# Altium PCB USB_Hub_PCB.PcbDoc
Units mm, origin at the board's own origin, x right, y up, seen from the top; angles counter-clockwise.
Board outline 110 x 90 mm, 2 copper layers (Top Layer, Bottom Layer); 74 components, 53 nets, 295 pads, 340 vias.
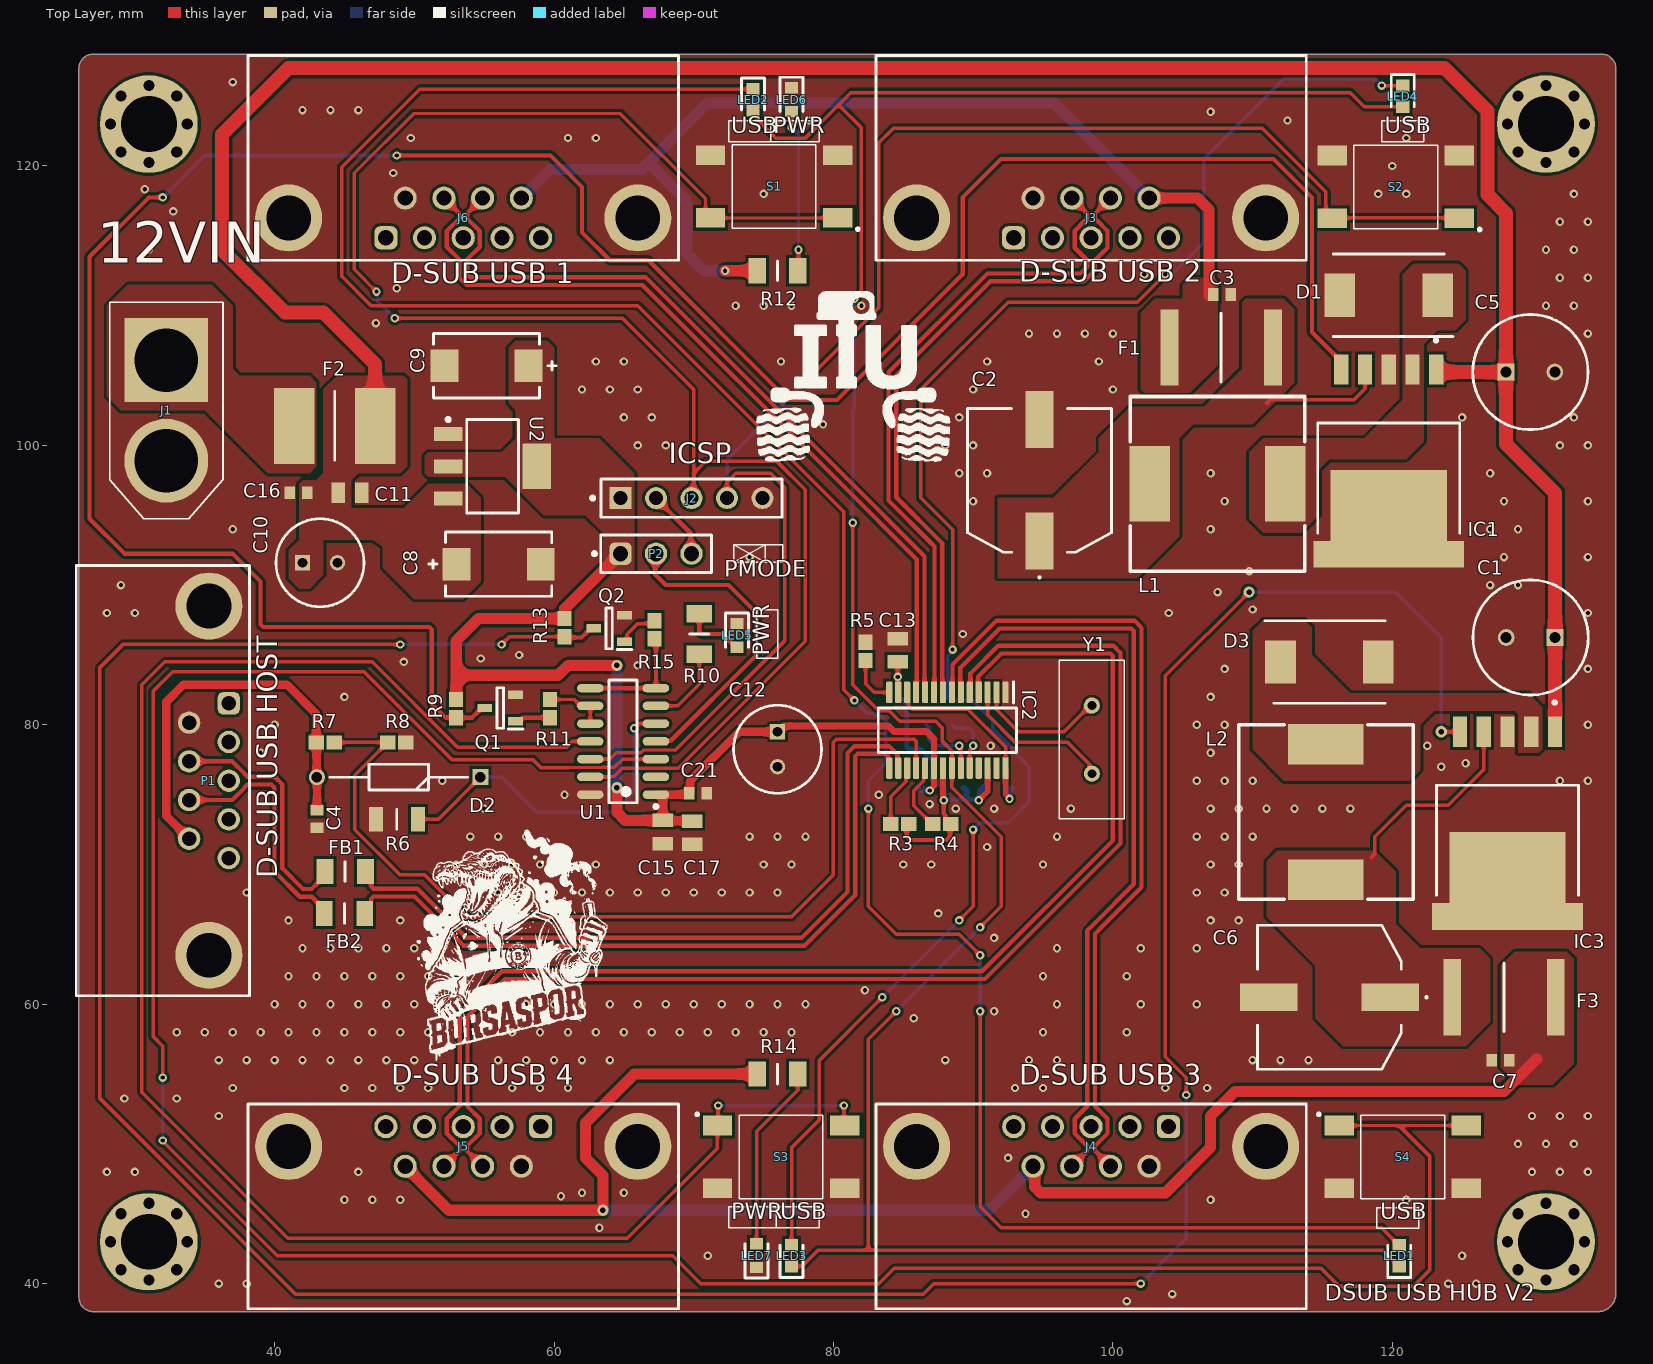
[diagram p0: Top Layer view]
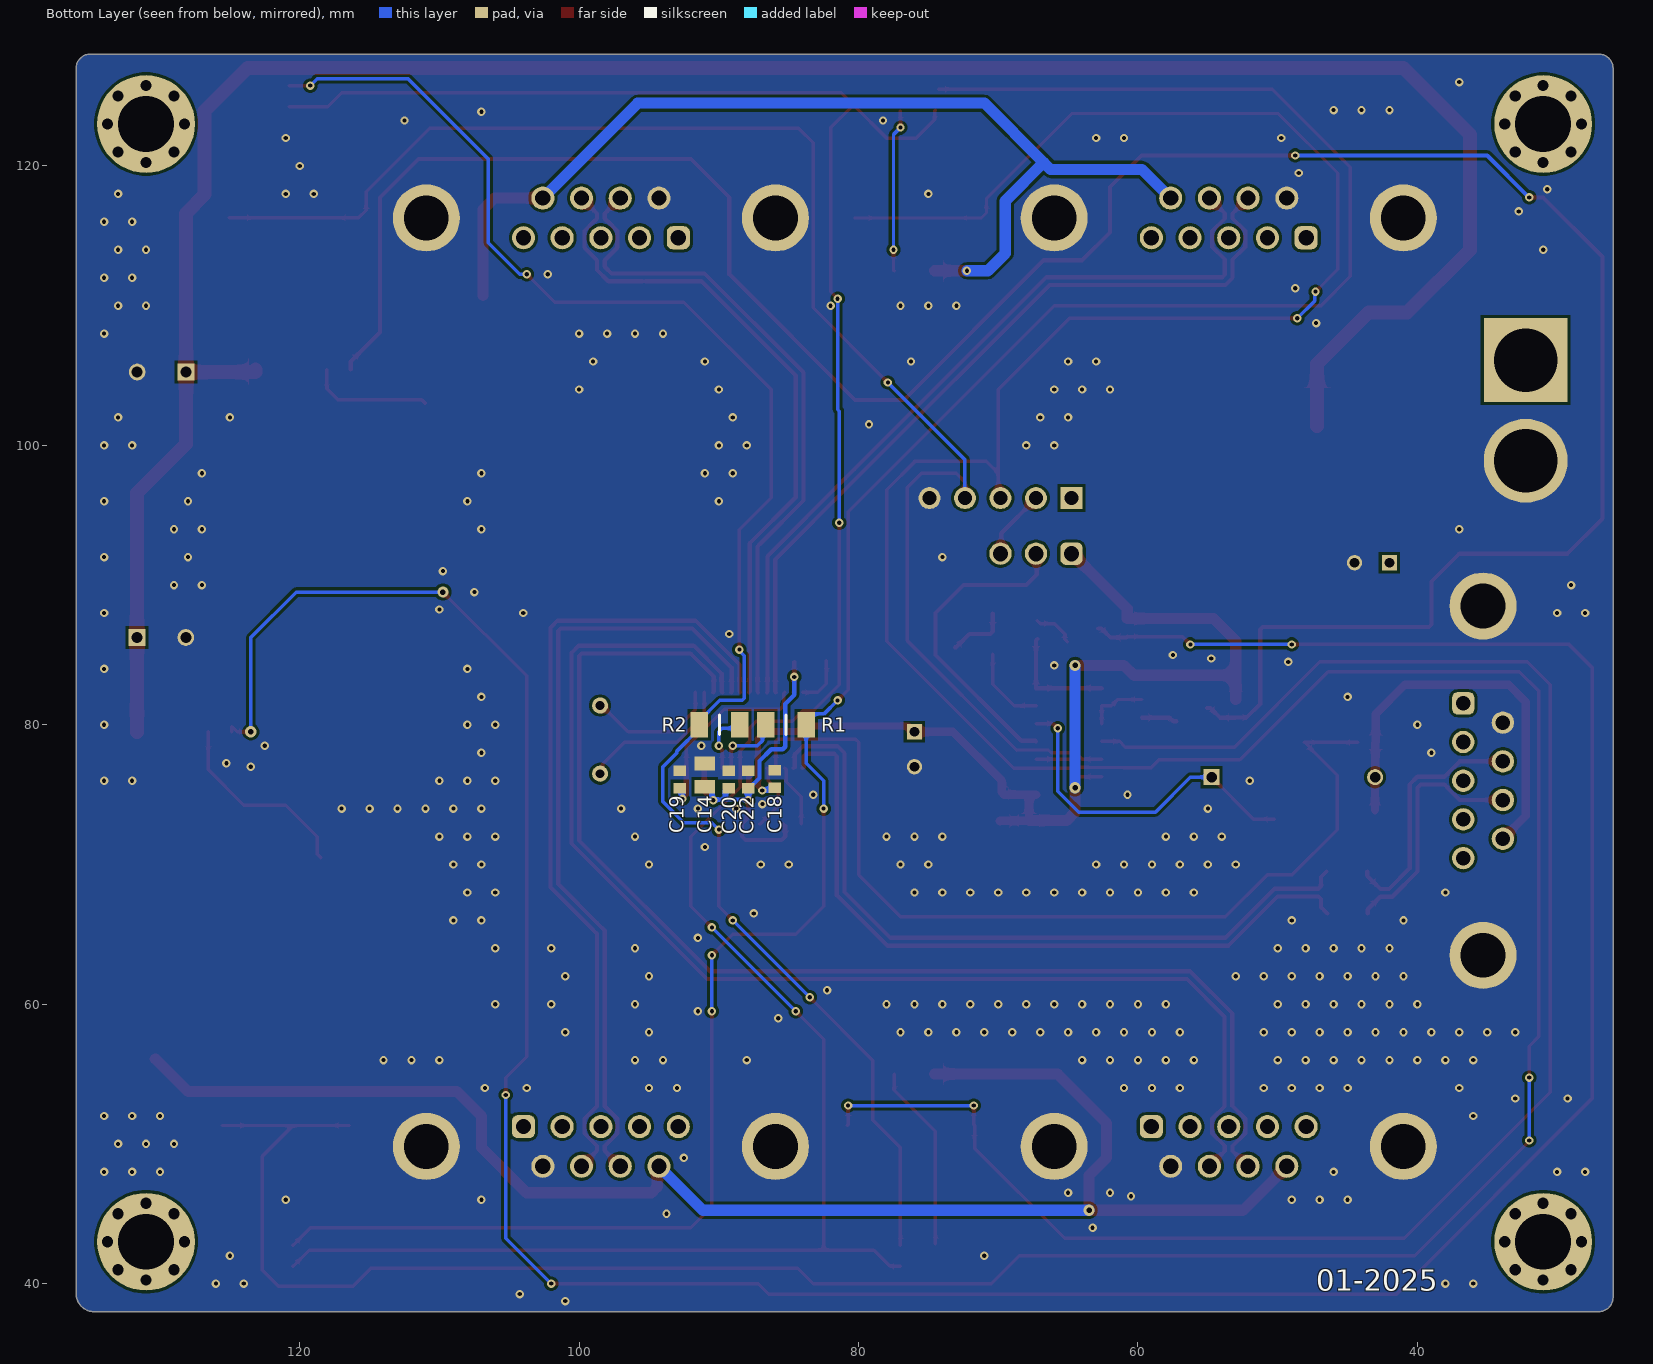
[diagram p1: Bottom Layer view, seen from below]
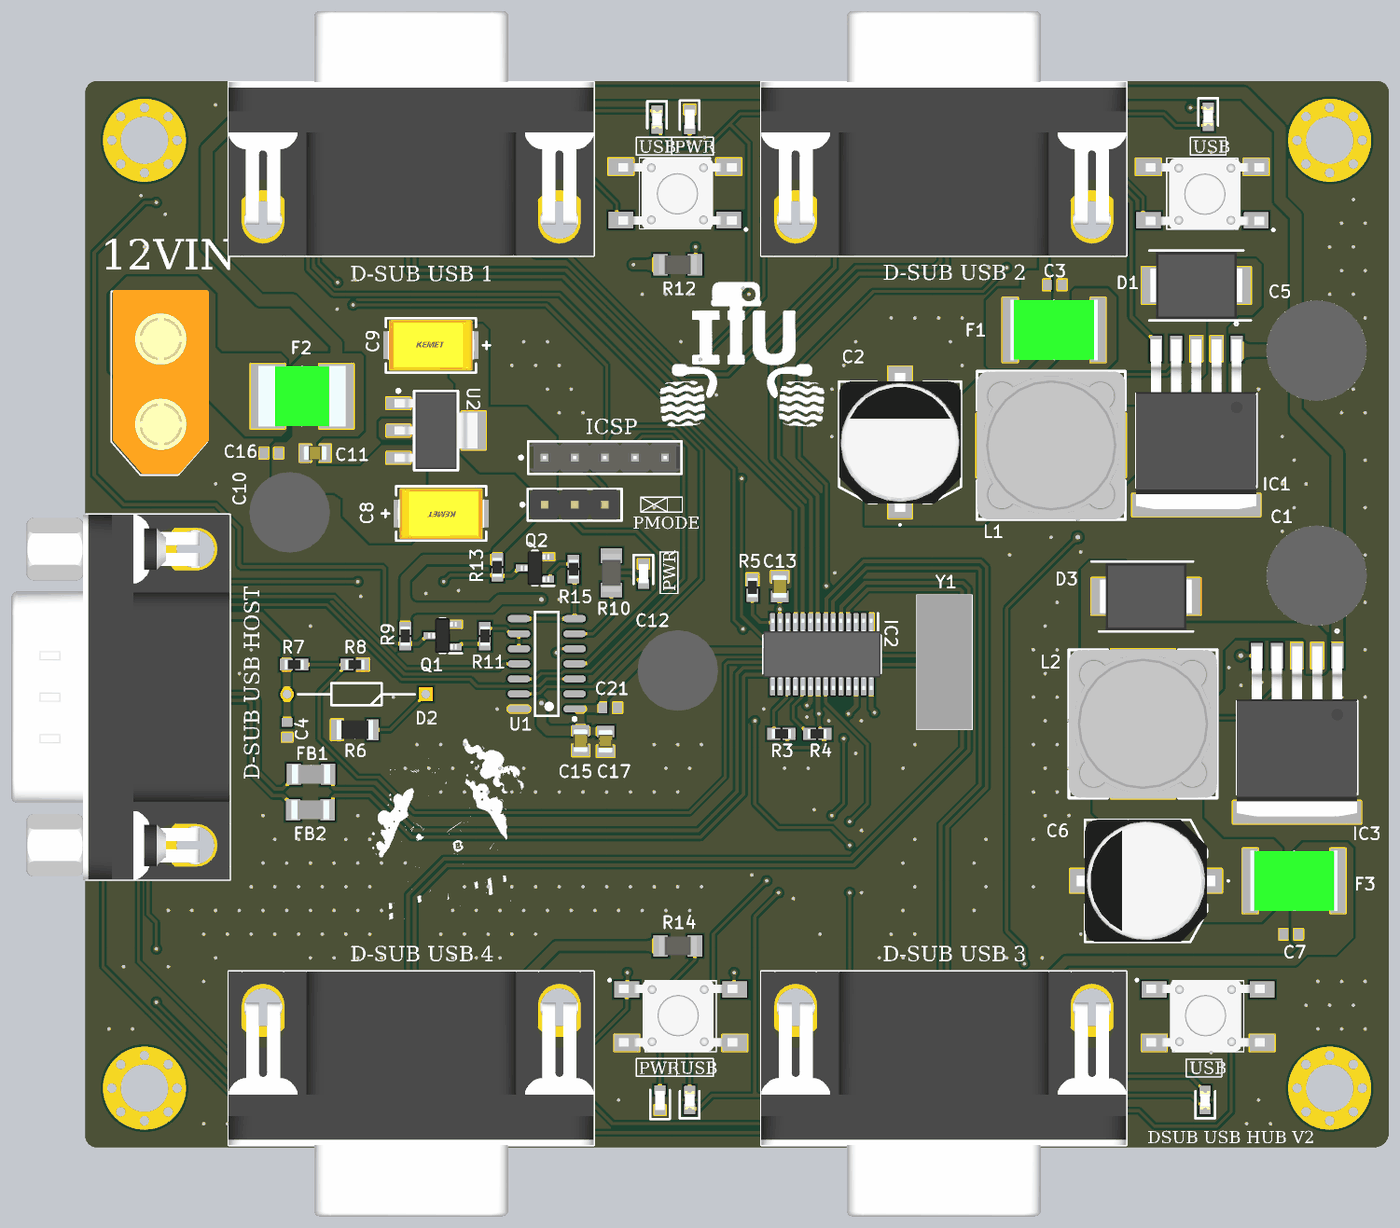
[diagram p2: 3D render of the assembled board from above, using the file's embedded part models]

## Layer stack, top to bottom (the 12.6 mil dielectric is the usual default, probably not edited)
Top Solder: solder mask 0.2, Solder Resist, Dk 3.5
Top Layer: signal copper 0.0356
Dielectric 1: dielectric 0.32, FR-4, Dk 4.8
Bottom Layer: signal copper 0.0356
Bottom Solder: solder mask 0.2, Solder Resist, Dk 3.5

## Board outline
27,38 cw(c27,39) 26,39 26,127 cw(c27,127) 27,128 135,128 cw(c135,127) 136,127 136,39.27 cw(c134.73,39.27) 134.73,38

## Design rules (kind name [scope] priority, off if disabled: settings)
Clearance [All] p1: gap=0.2 ignorepadtopadclearanceinfootprint=FALSE
DiffPairsRouting [All] p1: maxlimit=0.25 minlimit=0.25 mostfreqgap=0.25 toplayer_minwidth=0.305 toplayer_maxwidth=0.305 toplayer_prefwidth=0.305 bottomlayer_minwidth=0.305 bottomlayer_maxwidth=0.305 bottomlayer_prefwidth=0.305 impedanceprofiledriven=TRUE impedanceprofileid={82985F45-E5DD-44E9-867F-111D7A09A1A5} impedanceprofilevalue=90.000000 maxuncoupledlength=12.7
HoleSize [All] p1: absolutevalues=TRUE maxlimit=5 minlimit=0.3 maxpercent=80.000 minpercent=20.000
HoleToHoleClearance [All] p1: gap=0.25 allowstackedmicrovias=TRUE
MinimumSolderMaskSliver [All] p1: minsoldermaskwidth=0.25
PolygonConnect [All] p1: connectstyle=Direct reliefconductorwidth=0.254 reliefentries=4 polygonreliefangle="90 Angle" airgapwidth=0.254
RoutingVias [All] p1: holewidth=0.3 width=0.6 viastyle="Through Hole" minholewidth=0.3 minwidth=0.5 maxholewidth=0.8 maxwidth=1
SilkToSilkClearance [All] p1: silktosilkclearance=0.13
SilkToSolderMaskClearance [IsPad] p1: minsilkscreentomaskgap=0.13 clearancetoexposedcopper=TRUE
SolderMaskExpansion [All] p1: expansion=0.102 istentingtop=FALSE
SupplyNets "Schematic Supply Nets_4" [InNet('+12V')] p1: voltage=0.000
SupplyNets "Schematic Supply Nets_3" [InNet('GND')] p2: voltage=0.000
SupplyNets "Schematic Supply Nets_2" [InNet('+3V3')] p3: voltage=0.000
SupplyNets "Schematic Supply Nets_1" [InNet('+1V8')] p4: voltage=0.000
SupplyNets "Schematic Supply Nets" [InNet('+5V')] p5: voltage=0.000
Width [All] p1: maxlimit=1 minlimit=0.2 preferedwidth=0.25 minimp=50.000000 maximp=50.000000 favimp=50.000000
24 further rules are at their usual default settings.

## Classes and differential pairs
differential pair HOSTCONN_D: +HOSTCONN_D_P -HOSTCONN_D_N
differential pair USB4_D: +USB4_D_P -USB4_D_N
differential pair USB3_D: +USB3_D_P -USB3_D_N
differential pair USB2_D: +USB2_D_P -USB2_D_N
differential pair USB1_D: +USB1_D_P -USB1_D_N
differential pair HOST_D: +HOST_D_P -HOST_D_N

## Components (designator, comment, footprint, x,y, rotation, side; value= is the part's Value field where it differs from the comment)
C1 "UPW1E471MPD6" CAPPRD350W60D825H2200 131.65,86.25 r180 top
C2 "220µF 50V" EEEFK1V331P 94.75,97.5 r0 top
C3 "VJ0603Y104JXJAC" CAPC1608X92X38LL15T08 107.8,110.8 r180 top
C4 "VJ0603Y104JXJAC" CAPC1608X92X38LL15T08 43.034,73.25 r90 top
C5 "UPW1E471MPD6" CAPPRD350W60D825H2200 128.138,105.25 r0 top
C6 "220µF 50V" EEEFK1V331P 115.5,60.5 r90 top
C7 "VJ0603Y104JXJAC" CAPC1608X92X38LL15T08 127.75,56 r0 top
C8 "10uF Tantal" FP-T491D-MFG 56.035,91.5 r180 top
C9 "10uF Tantal" FP-T491D-MFG 55.165,105.7 r0 top
C10 "860020473008" CAPPRD250W52D630H1250 42,91.6 r0 top
C11 "CL21A106KAYNNNG" CAPC2012X145N 45.4,96.6 r180 top
C12 "860020473008" CAPPRD250W52D630H1250 76,79.5 r270 top
C13 "CL21A106KAYNNNG" CAPC2012X145N 84.6,85.33 r270 top
C14 "CL21A106KAYNNNG" CAPC2012X145N 91,76.4 r270 bottom
C15 "CL21A106KAYNNNG" CAPC2012X145N 67.8,72.33 r90 top
C16 "VJ0603Y104JXJAC" CAPC1608X92X38LL15T08 41.7,96.6 r0 top
C17 "CL21A106KAYNNNG" CAPC2012X145N 69.9,72.27 r90 top
C18 "VJ0603Y104JXJAC" CAPC1608X92X38LL15T08 86,76.125 r270 bottom
C19 "VJ0603Y104JXJAC" CAPC1608X92X38LL15T08 92.8,76.1 r270 bottom
C20 "VJ0603Y104JXJAC" CAPC1608X92X38LL15T08 89.3,76.1 r270 bottom
C21 "VJ0603Y104JXJAC" CAPC1608X92X38LL15T08 70.3,75.1 r180 top
C22 "VJ0603Y104JXJAC" CAPC1608X92X38LL15T08 87.9,76.1 r270 bottom
D1 "B540C-13-F" DIOM7959X250N 119.75,110.75 r180 top
D2 "1N4148,133" DIOAD1165W56L425D185 54.734,76.25 r180 top
D3 "B540C-13-F" DIOM7959X250N 115.5,84.5 r0 top
F1 "MF-LSMF300X-2" FUSC7451X85N 107.75,107 r180 top
F2 "2920L600_16MR" FUSC7451X160N 44.3,101.4 r0 top
F3 "MF-LSMF300X-2" FUSC7451X85N 128,60.5 r0 top
FB1 "HI1206T500R-10" BEADC3216X130N 45.05,69.5 r0 top
FB2 "HI1206T500R-10" BEADC3216X130N 45,66.5 r180 top
IC1 "LM2596S-5.0" KTT0005B 119.75,92.964 r90 top
IC2 "FE1.1S" SOP64P600X175-28N 88.16,79.612 r270 top
IC3 "LM2596S-5.0" KTT0005B 128.25,67.039 r90 top
J1 "XT60-M" XT60-M-Footprint-1 32.25,102.5 r270 top
J2 "22-28-4050" FP-22-28-4050-MFG 69.843,96.225 r0 top
J3 "618009233821" 618009233821 98.445,120.625 r180 top
J4 "618009233821" 618009233821 98.445,45.475 r0 top
J5 "618009233821" 618009233821 53.505,45.475 r0 top
J6 "618009233821" 618009233821 53.505,120.625 r180 top
L1 "SRR1260-330M" SRR1260-150M 107.5,97.25 r180 top
L2 "SRR1260-330M" SRR1260-150M 115.25,73.75 r270 top
LED1 "LTST-C190GKT" LEDC1608X90N 120.499,42 r90 top
LED2 "LTST-C190GKT" LEDC1608X90N 74.25,124.75 r270 top
LED3 "LTST-C190GKT" LEDC1608X90N 77,42 r90 top
LED4 "LTST-C190GKT" LEDC1608X90N 120.75,125 r270 top
LED5 "TLMS1000-GS08" LEDC1608X65N 73.1,86.4 r270 top
LED6 "TLMS1000-GS08" LEDC1608X65N 77,124.75 r270 top
LED7 "TLMS1000-GS08" LEDC1608X65N 74.5,42 r90 top
P1 "618009231221" 618009231221 32,76 r270 top
P2 "61300311121" 61300311121 67.303,92.25 r0 top
Q1 "PMBT3904,235" SOT95P230X110-3N 56.15,81.2 r180 top
Q2 "PMBT3904,235" SOT95P230X110-3N 63.95,86.9 r180 top
R1 "RMCF1206JT2K20" RESC3216X70N 85.2,80 r0 bottom
R2 "RMCF1206JT2K20" RESC3216X70N 89.95,80 r180 bottom
R3 "RC0603FR-07100KL" RESC1608X55N 84.75,72.9 r0 top
R4 "RC0603FR-07100KL" RESC1608X55N 87.75,72.9 r0 top
R5 "RC0603JR-072K7L" RESC1608X55N 82.3,85.25 r270 top
R6 "RC1206FR-0747KL" RESC3116X65N 48.75,73.25 r0 top
R7 "RC0603FR-0751KL" RESC1608X55N 43.634,78.75 r0 top
R8 "RC0603FR-07100KL" RESC1608X55N 48.75,78.75 r180 top
R9 "RC0603FR-0724K9L" RESC1608X55N 53,81.161 r90 top
R10 "RMCF1206JT2K20" RESC3216X70N 70.4,86.5 r90 top
R11 "10K" RESC1608X55N 59.722,81.161 r270 top
R12 "CR1206-JW-512ELF" RESC3216X70N 75.999,112.5 r0 top
R13 "RC0603FR-0724K9L" RESC1608X55N 60.765,86.961 r90 top
R14 "CR1206-JW-512ELF" RESC3216X70N 76.001,55 r0 top
R15 "10K" RESC1608X55N 67.2,86.8 r90 top
S1 "TL3301AF160QG" TL3301AF160QG 75.75,118.53 r90 top
S2 "TL3301AF160QG" TL3301AF160QG 120.25,118.5 r90 top
S3 "TL3301AF160QG" TL3301AF160QG 76.25,49.07 r270 top
S4 "TL3301AF160QG" TL3301AF160QG 120.748,49.07 r270 top
U1 "PIC16F630-I/SL" SOIC-SL14_L 64.944,78.814 r180 top
U2 "LM1117IMP-5.0-NOPB" DCY0004A_M 55.6,98.5 r0 top
Y1 "ECS-120-18-4X-CKM" ECS120184XCKM 98.5,76.5 r90 top

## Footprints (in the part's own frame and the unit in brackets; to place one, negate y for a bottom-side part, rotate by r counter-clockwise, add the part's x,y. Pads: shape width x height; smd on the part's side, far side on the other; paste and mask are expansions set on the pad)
61300311121 [mm] "Pin Header, pitch 2.54 mm, THT, Vertical, single row, 3p"
  rrect50% 1.6x1.6 hole 1.1: 1(-2.54,0)
  round 1.6 hole 1.1: 2(0,0) 3(2.54,0)
  silkscreen extent -4.53,-1.35 3.96,1.35, body extent -3.81,-1.27 3.81,1.27, height 8.57
618009231221 [mm] "9 pins, right angled, 8.08mm, with hex screw"
  rrect50% 1.6x1.6 hole 1.04: 1(-5.54,4.72)
  round 1.6 hole 1.04: 2(-2.77,4.72) 3(0,4.72) 4(2.77,4.72) 5(5.54,4.72) 6(-4.155,1.88) 7(-1.385,1.88) 8(1.385,1.88) 9(4.155,1.88)
  round 4.8 hole 3.2: M1(-12.5,3.3) M2(12.5,3.3)
  silkscreen extent -15.4,-6.2 15.4,6.2, body extent -15.4,-12.2 15.4,6.2, height 12.57
618009233821 [mm] "09p 10.3mm bracket, board lock & UNC4-40 Rivet without hex screw"
  rrect50% 1.65x1.65 hole 1.09: 1(5.54,5.765)
  round 1.65 hole 1.09: 2(2.77,5.765) 3(0,5.765) 4(-2.77,5.765) 5(-5.54,5.765) 6(4.155,2.925) 7(1.385,2.925) 8(-1.385,2.925) 9(-4.155,2.925)
  round 4.8 hole 3.2: M1(-12.495,4.345) M2(12.495,4.345)
  silkscreen extent -15.4,-7.27 15.4,7.37, body extent -15.41,-13.27 15.41,7.37, height 12.57
BEADC3216X130N [mm]
  rect 1.2x1.8 smd: 1(-1.45,0) 2(1.45,0)
  silkscreen extent 0,-0.7 0,0.7, body extent -1.6,-0.8 1.6,0.8, height 1.3
CAPC1608X92X38LL15T08 [mm] "Chip Capacitor, 2-Leads, Body 1.60x0.80mm, IPC High Density"
  rect 0.75x0.9 smd: 1(-0.625,0) 2(0.625,0)
  body extent -0.87,-0.48 0.87,0.48, height 0.92
CAPC2012X145N [mm]
  rect 0.97x1.47 smd: 1(-0.83,0) 2(0.83,0)
  body extent -1,-0.63 1,0.63, height 1.45
CAPPRD250W52D630H1250 [mm]
  rect 1.1x1.1 hole 0.7: 1(0,0)
  round 1.1 hole 0.7: 2(2.5,0)
  silkscreen extent -1.9,-3.15 4.4,3.15, body extent -2.14,-3.4 4.65,3.4, height 12.5
CAPPRD350W60D825H2200 [mm]
  rect 1.2x1.2 hole 0.8: 1(0,0)
  round 1.2 hole 0.8: 2(3.5,0)
  silkscreen extent -2.38,-4.12 5.87,4.12, body extent -2.49,-4.25 6,4.25, height 22
DCY0004A_M [mm] "SOT223, 4-Leads, Body 6.7x3.7mm, Pitch 2.3mm, IPC Low Density"
  rrect10% 2.05x1 smd: 1(-3.175,2.3) 2(-3.175,0) 3(-3.175,-2.3)
  rrect5% 2.05x3.25 smd: 4(3.175,0)
  silkscreen extent -3.3,-3.35 1.85,3.47, body extent -3.5,-3.25 3.5,3.25, height 1.62
DIOAD1165W56L425D185 [mm]
  rect 1.15x1.15 hole 0.75: 1(0,0)
  round 1.15 hole 0.75: 2(11.7,0)
  silkscreen extent 0.92,-0.92 10.78,0.92
DIOM7959X250N [mm]
  rect 2.2x3.1 smd: 1(-3.5,0) 2(3.5,0)
  silkscreen extent -4.6,-2.95 3.97,2.95, body extent -3.9,-2.81 3.9,2.81, height 2.5
ECS120184XCKM [mm]
  round 1.155 hole 0.63: 1(0,0) 2(4.88,0)
  silkscreen extent -3.23,-2.32 8.12,2.32, body extent -3.23,-2.32 8.12,2.32, height 3.5
EEEFK1V331P [mm]
  rect 2x4.1 smd: 1(0,-4.35) 2(0,4.35)
  silkscreen extent -5.15,-7 5.15,5.15, body extent -5.15,-5.85 5.15,5.85, height 10.2
FP-22-28-4050-MFG [mm]
  rect 1.57x1.57 hole 1.02 paste-2539.97 mask+0: 1(-5.08,0)
  round 1.57 hole 1.02 paste-2539.97 mask+0: 2(-2.54,0) 3(0,0) 4(2.54,0) 5(5.08,0)
  silkscreen extent -7.2,-1.37 6.48,1.37, body extent -6.58,-1.47 6.58,1.47, height 0.25
FP-T491D-MFG [mm]
  rect 1.99x2.33 smd paste+0 mask+0: 1(-3.01,0) 2(3.01,0)
  silkscreen extent -3.8,-2.3 5,2.3, body extent -4.13,-2.42 4.13,2.42, height 0.25
FUSC7451X85N [mm]
  rect 1.28x5.45 smd: 1(-3.705,0) 2(3.705,0)
  silkscreen extent 0,-2.46 0,2.46, body extent -3.68,-2.56 3.68,2.56, height 0.85
FUSC7451X160N [mm]
  rect 2.9x5.45 smd: 1(-2.89,0) 2(2.89,0)
  silkscreen extent 0,-2.46 0,2.46, body extent -3.68,-2.56 3.68,2.56, height 1.6
KTT0005B [mm]
  rect 2.16x1.02 smd: 1(12.461,-3.4) 2(12.461,-1.7) 3(12.461,0) 4(12.461,1.7) 5(12.461,3.4)
  rect 1.91x1.235 smd: 6(-0.754,4.782) 6(-0.754,-4.782)
  rect 6.99x8.33 smd: 6(1.786,0)
  silkscreen extent 0.76,-5.08 14.68,5.08, body extent -1.11,-5.08 13.24,5.08, height 4.72
LEDC1608X65N [mm]
  rect 0.8x0.95 smd: 1(-0.85,0) 2(0.85,0)
  silkscreen extent -1.6,-0.82 0.85,0.82, body extent -0.83,-0.4 0.77,0.4, height 0.65
LEDC1608X90N [mm]
  rect 0.9x0.95 smd: 1(-0.75,0) 2(0.75,0)
  silkscreen extent -1.55,-0.82 0.75,0.82, body extent -0.82,-0.4 0.78,0.4, height 0.8
RESC1608X55N [mm]
  rect 1.1x1 smd: 1(-0.65,0) 2(0.65,0)
  body extent -0.8,-0.4 0.8,0.4, height 0.55
RESC3116X65N [mm]
  rect 1x1.75 smd: 1(-1.5,0) 2(1.5,0)
  silkscreen extent 0,-0.7 0,0.7, body extent -1.55,-0.8 1.55,0.8, height 0.65
RESC3216X70N [mm]
  rect 1.25x1.8 smd: 1(-1.45,0) 2(1.45,0)
  silkscreen extent 0,-0.7 0,0.7, body extent -1.6,-0.8 1.6,0.8, height 0.55
SOIC-SL14_L [mm] "SOIC, 14-Leads, Body 8.7x3.9mm, Pitch 1.27mm, IPC High Density"
  oval 1.9x0.6 smd: 1(-2.35,3.81) 2(-2.35,2.54) 3(-2.35,1.27) 4(-2.35,0) 5(-2.35,-1.27) 6(-2.35,-2.54) 7(-2.35,-3.81) 8(2.35,-3.81) 9(2.35,-2.54) 10(2.35,-1.27) 11(2.35,0) 12(2.35,1.27) 13(2.35,2.54) 14(2.35,3.81)
  silkscreen extent -2.48,-4.4 1,4.78, body extent -2,-4.38 2,4.38, height 1.75
SOP64P600X175-28N [mm]
  rrect30% 1.525x0.44 smd mask+0.1: 1(-2.712,4.16) 2(-2.712,3.52) 3(-2.712,2.88) 4(-2.712,2.24) 5(-2.712,1.6) 6(-2.712,0.96) 7(-2.712,0.32) 8(-2.712,-0.32) 9(-2.712,-0.96) 10(-2.712,-1.6) 11(-2.712,-2.24) 12(-2.712,-2.88) 13(-2.712,-3.52) 14(-2.712,-4.16) 15(2.712,-4.16) 16(2.712,-3.52) 17(2.712,-2.88) 18(2.712,-2.24) 19(2.712,-1.6) 20(2.712,-0.96) 21(2.712,-0.32) 22(2.712,0.32) 23(2.712,0.96) 24(2.712,1.6) 25(2.712,2.24) 26(2.712,2.88) 27(2.712,3.52) 28(2.712,4.16)
  silkscreen extent -3.47,-4.95 1.6,4.95, body extent -3,-4.95 3,4.95, height 1.75
SOT95P230X110-3N [mm]
  rect 1.05x0.6 smd: 1(-1.1,0.95) 2(-1.1,-0.95) 3(1.1,0)
  silkscreen extent -1.63,-1.45 0.23,1.5, body extent -1.2,-1.45 1.2,1.45, height 0.95
SRR1260-150M [mm]
  rect 2.9x5.4 smd: 1(-4.85,0) 2(4.85,0)
  silkscreen extent -6.25,-6.25 6.25,6.25, body extent -6.25,-6.25 6.25,6.25, height 6
TL3301AF160QG [mm]
  rect 1.4x2.1 smd: 1(-2.25,-4.55) 2(-2.25,4.55) 3(2.25,-4.55) 4(2.25,4.55)
  silkscreen extent -3.1,-6.05 3,3, body extent -3.05,-5.22 2.95,4.78, height 5.1
XT60-M-Footprint-1 [mm]
  round 6 hole 4.55: N(3.6,0)
  rect 6x6 / inner round 6 / far side rect 6x6 hole 4.55: P(-3.6,0)
  silkscreen extent -7.75,-4.05 7.75,4.05, body extent -7.88,-3.92 7.62,4.18, height 16

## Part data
C1 C5: "Capacitor Polarised", Manufacturer_Name=Nichicon, Mouser Part Number=647-UPW1E471MPD6
C2 C6: library part EEE-1HA221P, "Capacitor Polarised / EEE-1HA221P", Manufacturer_Name=Panasonic, Mouser Part Number=667-EEE-1HA221P
C3 C4 C7 C16 C18 C19 C20 C21 C22: library part CMP-001-00083-1, "Cap Ceramic 0.1uF 16V X7R 5% SMD 0603 150°C Paper T/R"
C8 C9: library part CMP-001-00086-1, "Cap Tant Solid 10uF 25V D CASE 10% (7.3 X 4.3 X 2.8mm) Inward L SMD 7343-31 1 Ohm 125C T/R / T491D106K025AT"
C10 C12: "Capacitor Polarised", Manufacturer_Name="Wurth Elektronik", Mouser Part Number=710-860020473008
C11 C13 C14 C15 C17: "Capacitor", Manufacturer_Name=SAMSUNG, Mouser Part Number=187-CL21A106KAYNNNG
D1 D3: "Diode", Manufacturer_Name="Diodes Incorporated", Mouser Part Number=621-B540C-F
D2: "Diode", Manufacturer_Name=Nexperia, Mouser Part Number=771-1N4148,133
F1 F3: "Fuse", Manufacturer_Name=Bourns, Mouser Part Number=652-MF-LSMF300X-2
F2: "Resettable Fuse", Arrow Part Number=2920L600/16MR, Manufacturer_Name=LITTELFUSE, Mouser Part Number=576-2920L600/16MR
FB1 FB2: "Ferrite Bead", Manufacturer_Name="Laird Technologies", Mouser Part Number=N/A
IC1 IC3: "Integrated Circuit", Manufacturer_Name="Texas Instruments", Mouser Part Number=926-LM2596S-50
IC2: "Integrated Circuit", Manufacturer_Name="JFD IC"
J1: library part CMP-002-00074-2, "XT60 Male Connector"
J2: library part CMP-00257-00278173-1, "22-28-4050 KK® 254 Breakaway Header, Vertical, 5 Circuits, Tin (Sn) Plating, Mating Pin Length 6.09mm", Color=Black, Contact Resistance=20mΩ, Current Rating=4A, Flammability Rating="UL94 V-0", Max Operating Temperature=75°C, Max Voltage Rating (DC)=250.25kV, Min Operating Temperature=0°C, Voltage Rating=250V
J3 J4 J5 J6: library part CMP-03913-89205522-1, "618009233821 D-Sub, 10.30mm Female Angled PCB Connector without Hex Screw, 9 pins", Contact Resistance=30mΩ, Current Rating=3A, Max Operating Temperature=105°C, Min Operating Temperature=-55°C, Operating Supply Voltage=125V, Insulation Resistance=5GΩ
L1 L2: "Inductor", Manufacturer_Name=Bourns, Mouser Part Number=652-SRR1260-330M
LED1 LED2 LED3 LED4: "LED", Manufacturer_Name=Lite-On, Mouser Part Number=859-LTST-C190GKT
LED5 LED6 LED7: "LED", Manufacturer_Name=Vishay, Mouser Part Number=78-TLMS1000
P1: library part CMP-1502-00284-2, Contact Resistance=30mΩ, Current Rating=3A, Max Operating Temperature=105°C, Min Operating Temperature=-55°C, Operating Supply Voltage=125V, Insulation Resistance=5GΩ
P2: library part CMP-1502-01062-3, Color=Black, Contact Resistance=20mΩ, Current Rating=3A, Max Operating Temperature=105°C, Min Operating Temperature=-40°C, Operating Supply Voltage=250V
Q1 Q2: "Transistor BJT NPN", Manufacturer_Name=Nexperia, Mouser Part Number=771-PMBT3904235
R1 R2: "Resistor", Manufacturer_Name="Stackpole Electronics", Mouser Part Number=708-RMCF1206JT2K20
R3 R4 R8: "Resistor", Manufacturer_Name=YAGEO, Mouser Part Number=603-RC0603FR-07100KL
R5: "Resistor", Manufacturer_Name=KEMET, Mouser Part Number=603-RC0603JR-072K7L
R6: "Resistor", Manufacturer_Name=YAGEO, Mouser Part Number=603-RC1206FR-0747KL
R7: "Resistor", Manufacturer_Name=KEMET, Mouser Part Number=603-RC0603FR-0751KL
R9 R13: "Resistor", Manufacturer_Name=YAGEO, Mouser Part Number=603-RC0603FR-0724K9L
R10: "Resistor 5.1K 1206", Manufacturer_Name="Stackpole Electronics", Mouser Part Number=708-RMCF1206JT2K20
R11 R15: library part RC0603FR0710KL, "RC0603FR0710KL", Manufacturer_Name=KEMET
R12: library part RMCF1206JT2K20, "Resistor 5.1K 1206", Manufacturer_Name="Stackpole Electronics", Mouser Part Number=708-RMCF1206JT2K20
R14: library part RMCF1206JT2K20, "Resistor  5.1K 1206", Manufacturer_Name="Stackpole Electronics", Mouser Part Number=708-RMCF1206JT2K20
S1 S2 S3 S4: "Switch", Manufacturer_Name=E-Switch, Mouser Part Number=612-TL3301AF1
U1: library part CMP-0115-01006-1, "FLASH-Based 8-Bit CMOS Microcontroller, 1K (x14-Bit words) FLASH, 64 Bytes SRAM, 14-Pin SOIC, 2.0 to 5.5V Supply Range, Industrial Temperature"
U2: library part CMP-019-00021-3, "Low-Dropout Linear Regulator, 800 mA, -40 to 125 degC, 4-Pin SOT-223 (DCY), Green (RoHS & no Sb/Br), Tape and Reel", Case/Package=SOT-223, Dropout Voltage=1.2V, Manufacturer="Texas Instruments", Max Operating Temperature=125°C, Max Ouput Current=800mA, Max Input Voltage=15V, Min Operating Temperature=-40°C, Min Input Voltage=2.6V, Nominal Output Voltage=5V, Package Description="4-Pin Small Outline Transistor, Body 6.5 x 3.5 mm, Pitch 2.3 mm", Package Reference=DCY0004A
Y1: "Crystal or Oscillator", Manufacturer_Name=ECS, Mouser Part Number=520-ECS120-18-4X-CKM

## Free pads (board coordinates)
  round 0 hole 0.8: 3(31,40.25) 3(31,120.25) 3(131,40.25) 3(131,120.25) 4(33.75,43) 4(33.75,123) 4(133.75,43) 4(133.75,123) 5(28.25,43) 5(28.25,123) 5(128.25,43) 5(128.25,123) 6(31,45.75) 6(31,125.75) 6(131,45.75) 6(131,125.75) 7(33,45) 7(33,125) 7(133,45) 7(133,125) 8(29,45) 8(29,125) 8(129,45) 8(129,125) 9(29,41) 9(29,121) 9(129,41) 9(129,121) 10(33,41) 10(33,121) 10(133,41) 10(133,121)
  round 7 hole 4 paste-2539.97 mask+0: ""(31,43) ""(31,123) ""(131,43) ""(131,123)

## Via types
v1: diameter 0.6, hole 0.3, Top Layer to Bottom Layer, tented both sides, 334 vias
v2: diameter 0.8, hole 0.4, Top Layer to Bottom Layer, tented both sides, 5 vias
v3: diameter 0.6, hole 0.3, Top Layer to Bottom Layer, 1 vias

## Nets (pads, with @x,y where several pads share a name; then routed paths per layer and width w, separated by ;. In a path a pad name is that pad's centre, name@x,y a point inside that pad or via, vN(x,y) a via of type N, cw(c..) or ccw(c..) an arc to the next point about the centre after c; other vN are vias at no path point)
+1V8: C19.2 IC2.12 IC2.28 | length 13.9
  Top Layer w0.25: IC2.12 85.366,82.238 85.366,81.384 85.625,81.125 89.625,81.125 92.32,78.43 IC2.28
  Top Layer w0.4: IC2.28 92.32,75.034 92.6,74.754 v1(92.6,74.7)
  Bottom Layer w0.4: v1(92.6,74.7) 92.638,74.738 92.638,75.313 C19.2
+3V3: C13.2 C14.2 C20.2 C22.2 IC2.13 IC2.21 IC2.26 R3.2 R4.2 | length 29.8
  Top Layer w0.3: C13.2 v1(84.6,83.432) 84.6,82.364 ccw(c84.64,82.364) IC2.13 ; R3.2 85.25,72.75 85.25,72 85.5,71.75 88.1,71.75 88.35,72 88.35,72.9 88,73.25 88,73.545 87.9,73.645 v1(87.9,74.6)
  Top Layer w0.4: IC2.21 87.84,74.714 87.9,74.654 v1(87.9,74.6) ; v1(90.4,74.6) 91.04,75.24 IC2.26
  Bottom Layer w0.3: v1(84.6,83.432) 84.6,82.15 85.25,81.5 85.25,78.426 85.426,78.25 86.25,78.25 87.1,77.4 87.1,76.2 87.825,75.475 C22.2 ; v1(87.9,74.6) 87.95,74.65 89.719,74.65 90.35,74.65 v1(90.4,74.6)
  Bottom Layer w0.4: v1(87.9,74.6) C22.2 ; C20.2 89.359,75.475 89.534,75.3 89.534,74.835 89.719,74.65 ; v1(90.4,74.6) 90.4,74.654 90.48,74.734 90.48,75.285 90.765,75.57 C14.2
+5V: C9.2 C12.1 C15.2 C17.2 C18.2 C21.2 IC2.20 J2.1 P2.1 R9.2 R13.2 U1.1 U2.2 U2.4 | length 76.3
  Top Layer w0.4: v1(86.9,75.3) 86.9,75.327 87.2,75.627 IC2.20 87.2,78.978
  Top Layer w0.5: C12.1 76.427,79.927 83.928,79.927 84.328,79.527 86.651,79.527 87.2,78.978
  Top Layer w0.6: U1.1 U1.1@67.8,75.004 ; C17.2 69.87,73.13 67.83,73.13 C15.2 U1.1@67.8,75.004 ; C12.1 73.25,79.5 69.75,76 69.75,75.175 C21.2 69.675,75.079 69.6,75.004 U1.1@67.8,75.004
  Top Layer w0.8: R9.2 53,83.546 ; v2(64.5,75.5) 64.5,73.746 65.086,73.16 C15.2 ; v2(64.5,84.25) 61,84.25 60.296,83.546 53,83.546 ; P2.1@64.71,92.25 60.765,88.305 R13.2 54.611,87.611 53,86 53,83.546
  Bottom Layer w0.4: C18.2 86.162,75.338 86.862,75.338 v1(86.9,75.3)
  Bottom Layer w0.8: v2(64.5,75.5) v2(64.5,84.25)
+12V: C1.1 C5.1 C8.2 C10.1 C11.2 C16.2 F2.2 IC1.1 IC3.1 U2.3 | length 172.4
  Top Layer w1: F2.2 47.19,105.81 43.5,109.5 40.75,109.5 36.25,114 36.25,122.25 40.998,126.998 123.752,126.998 126.532,124.218 126.8,123.95 126.8,121.827 126.802,121.77 126.802,117.948 128.138,116.612 C5.1 ; IC1.1 123.15,105.26 123.16,105.25 C5.1 ; IC3.1 C1.1 131.65,96.6 128.138,100.112 C5.1
CH-Sense: IC2.18 R7.2 R8.2 | length 66.6
  Top Layer w0.25: R7.2 R8.2@48.05,78.75 ; R8.2 R8.2@48.05,78.75 ; IC2.18 85.92,78.805 85.774,78.952 80.202,78.952 80,78.75 80,69.25 77,66.25 53.75,66.25 50.75,69.25 49,69.25 45.75,72.5 45.75,76.4 47.675,78.325 47.675,78.375 R8.2@48.05,78.75
FB1: C2.1 F1.1 IC1.4 L1.2 | length 8.9
  Top Layer w0.25: 111,103 111.25,103.25 117.25,103.25 118.05,104.05 IC1.4
FB2: C6.1 F3.1 IC3.4 L2.2 | length 14.1
  Top Layer w0.25: 118.5,70.5 118.75,70.75 118.75,72 121,74.25 124,74.25 126.55,76.8 IC3.4
GND: C1.2 C2.2 C3.1 C4.1 C5.2 C6.2 C7.1 C8.1 C9.1 C10.2 C11.1 C12.2 C13.1 C14.1 C15.1 C16.1 C17.1 C18.1 C19.1 C20.1 C21.1 C22.1 D1.2 D3.2 IC1.3 IC1.6 IC2.1 IC3.3 IC3.6 J1.N J2.5 J3.6 J3.M1 J3.M2 J4.6 J4.M1 J4.M2 J5.6 J5.M1 J5.M2 J6.6 J6.M1 J6.M2 LED5.1 LED6.1 LED7.1 P1.6 P1.M1 P1.M2 Q1.2 Q2.2 R5.1 R6.1 R8.1 S1.3 S1.4 S2.3 S2.4 S3.3 S3.4 S4.3 S4.4 U1.14 U2.1
  other v1: 101,38.75 104.25,39.25 36,40 38,40 124,40 126,40 71,42 125,42 63.25,44 93.75,45 45,46 47,46 49,46 107,46 121,46 60.5,46.25 62,46.5 65,46.5 28,48 30,48 46,48 130,48 132,48 134,48 92.5,49 129,50 131,50 133,50 36,52 130,52 132,52 134,52 29.25,53.25 33,53.25 37,54 45,54 47,54 49,54 51,54 57,54 59,54 61,54 93,54 95,54 103.75,54 106.75,54 36,56 38,56 40,56 42,56 44,56 46,56 48,56 50,56 56,56 58,56 60,56 62,56 64,56 88,56 94,56 96,56 110,56 112,56 114,56 33,58 35,58 37,58 39,58 41,58 43,58 45,58 47,58 49,58 51,58 57,58 59,58 61,58 63,58 65,58 67,58 69,58 71,58 73,58 75,58 77,58 95,58 101,58 85.75,59 91.5,59.5 40,60 42,60 44,60 46,60 48,60 50,60 58,60 60,60 62,60 64,60 66,60 68,60 70,60 72,60 74,60 76,60 78,60 96,60 102,60 106,60 82.25,61 41,62 43,62 45,62 47,62 49,62 51,62 53,62 95,62 101,62 42,64 44,64 46,64 48,64 50,64 96,64 102,64 106,64 91.5,64.75 41,66 49,66 107,66 109,66 87.5,66.5 38,68 56,68 58,68 60,68 62,68 64,68 66,68 68,68 70,68 72,68 74,68 76,68 106,68 108,68 53,70 55,70 57,70 59,70 61,70 63,70 75,70 77,70 85,70 87,70 95,70 107,70 109,70 91,71.25 54,72 56,72 58,72 74,72 76,72 78,72 96,72 106,72 108,72 110,72 55,74 88.75,74 91.5,74 97,74 107,74 109,74 111,74 113,74 115,74 117,74 86.885,74.324 60.75,75 83.25,75 52,76 106,76 108,76 110,76 132,76 134,76 123.5,77 125.25,77.25 39,78 107,78 91.25,78.5 122.5,78.5 40,80 106,80 108,80 134,80 45,82 107,82 108,84 134,84 66,84.25 49.25,84.5 54.75,84.75 57.5,85 89.25,86.5 28,88 30,88 104,88 134,88 110,88.25 107.5,89.5 29,90 127,90 129,90 109.75,91 74,92 128,92 134,92 37,94 107,94 127,94 129,94 90,96 108,96 128,96 134,96 89,98 91,98 107,98 127,98 66,100 68,100 88,100 90,100 132,100 134,100 79.25,101.5 65,102 67,102 89,102 125,102 133,102 62,104 64,104 66,104 90,104 100,104 63,106 65,106 76.25,106 91,106 99,106 94,108 96,108 98,108 100,108 134,108 47.25,108.75 73,110 75,110 77,110 131,110 133,110 48.75,111.25 132,112 134,112 102.25,112.25 31,114 131,114 133,114 132,116 134,116 32.75,116.75 75,118 119,118 121,118 133,118 30.709,118.331 48.5,119.5 120,120 49.75,122 61,122 63,122 121,122 78.25,123.25 112.5,123.25 107,123.875 42,124 44,124 46,124 37,126
  other v3: 82,110
HOST_D_N: FB2.1 IC2.15 | length 52.2
  Top Layer w0.305: FB2.1 46.897,66.947 46.897,67.533 47.076,67.712 50.003,67.712 53.52,64.195 77.945,64.195 81.555,67.805 81.555,77.74 81.734,77.919 83.754,77.919 83.933,77.74 83.933,76.967 IC2.15
HOST_D_P: FB1.2 IC2.16 | length 53.2
  Top Layer w0.305: FB1.2 46.897,69.103 46.897,68.446 47.076,68.267 50.233,68.267 53.75,64.75 77.715,64.75 81,68.035 81,77.97 81.504,78.474 83.984,78.474 84.573,77.885 84.573,76.967 IC2.16
HOSTCONN_D_N: FB2.2 P1.8 | length 17.7
  Top Layer w0.305: P1.8 36.965,74.615 37.873,75.523 37.873,75.544 38.051,75.722 39.778,75.722 40,75.5 40,69.5 41.805,67.695 42.655,67.695 43.55,66.8 FB2.2
HOSTCONN_D_P: FB1.1 P1.7 | length 17.7
  Top Layer w0.305: P1.7 36.965,77.385 37.873,76.477 37.873,76.456 38.051,76.278 40.007,76.278 40.555,75.73 40.555,69.73 42.035,68.25 42.65,68.25 43.6,69.2 FB1.1
NetC4_2: C4.2 D2.2 P1.9 R7.1 | length 29.5
  Top Layer w0.6: P1.9 32.25,73.475 32.25,81.65 33.475,82.875 40.875,82.875 42.984,80.766 R7.1 43.009,78.725 43.009,76.275 D2.2 C4.2
NetD1_1: D1.1 IC1.2 L1.1
NetD3_1: D3.1 IC3.2 L2.1
NetF2_1: F2.1 J1.P
NetJ2_2: J2.2 P2.3 | length 5
  Top Layer w0.3: J2.2 67.303,96.197 69.79,93.71 P2.3@69.79,92.25
NetLED1_1: IC2.22 LED1.1 LED2.2 LED3.1 LED4.2 | length 186.9
  Top Layer w0.25: LED2.2@74.5,124 74.553,123.947 74.553,123.321 75.875,122 78,122 80.25,124.25 ; LED3.1 77.75,41.25 78.896,42.396 82.5,42.396 ; v1(81.384,94.456) 81.373,94.445 81.373,82.877 83.25,81 84,81 84.75,80.25 87.313,80.25 87.775,79.788 87.775,78.841 88.48,78.136 IC2.22 88.48,75.52 92,72 92,67 v1(90.5,65.5) ; v1(81.5,110.5) 82,111 82,122.75 80.5,124.25 80.25,124.25 ; v1(84.5,59.5) 82.5,57.5 82.5,42.396 ; LED1.1 120.475,41.25 119.329,42.396 82.5,42.396 ; LED4.2 118,124.25 117,125.25 81.25,125.25 80.25,124.25
  Bottom Layer w0.25: v1(81.384,94.456) 81.384,102.453 81.5,102.57 v1(81.5,110.5) ; v1(84.5,59.5) v1(90.5,65.5)
NetLED1_2: LED1.2 LED2.1 R1.1 | length 171.6
  Top Layer w0.25: LED2.1 50.4,125.5 44.8,119.9 44.8,112.1 46.9,110 66,110 80.75,95.25 80.75,82.5 v1(81.5,81.75) ; v1(82.5,74) 82.5,67 84.5,65 89,65 v1(90.5,63.5) ; v1(90.5,59.5) 90.5,45.5 92,44 119.225,44 120.475,42.75 LED1.2
  Bottom Layer w0.25: v1(81.5,81.75) 82.475,80.775 83.25,80.775 83.75,80.275 R1.1 83.75,77.25 82.5,76 v1(82.5,74) ; v1(90.5,59.5) v1(90.5,63.5)
NetLED3_2: LED3.2 LED4.1 R2.1 | length 121.3
  Top Layer w0.25: LED3.2 77,49.73 79,51.73 79,56 v1(83.5,60.5) ; v1(88.532,85.383) 88.532,93.968 86.25,96.25 86.25,104 92.5,110.25 101.75,110.25 v1(103.75,112.25) ; v1(89,66) 90,67 v1(90,72.5) ; v1(119.25,125.75) LED4.1
  Bottom Layer w0.25: v1(83.5,60.5) v1(89,66) ; v1(88.532,85.383) 88.532,85.288 88.176,84.932 88.176,81.896 88.322,81.75 89.925,81.75 91.4,80.275 R2.1 91.4,79.725 93,78.125 93,78 94,77 94,74.5 92.5,73 90.5,73 v1(90,72.5) ; v1(103.75,112.25) 104.25,112.25 106.5,114.5 106.5,120.5 112.25,126.25 118.75,126.25 v1(119.25,125.75)
NetLED5_2: LED5.2 R10.2 | length 4.4
  Top Layer w0.305: R10.2 70.4,86.679 70.579,86.5 72.075,86.5 73.025,85.55 LED5.2
NetLED6_2: LED6.2 R12.2 | length 11.6
  Top Layer w0.25: v1(77,122.75) LED6.2 ; R12.2 77.5,112.55 v1(77.5,114)
  Bottom Layer w0.25: v1(77,122.75) 77.5,122.25 v1(77.5,114)
NetLED7_2: LED7.2 R14.2 | length 13.4
  Top Layer w0.25: LED7.2 74.5,50.902 77.451,53.852 R14.2
NetQ1_1: Q1.1 R11.2 | length 2.6
  Top Layer w0.305: Q1.1 57.475,80.25 57.736,80.511 R11.2
NetQ2_1: Q2.1 R15.2 | length 3
  Top Layer w0.25: Q2.1 65.054,85.95 65.229,86.125 65.229,86.479 66,87.25 67,87.25 R15.2
NetR1_2: IC2.23 R1.2 | length 5.1
  Top Layer w0.25: v1(89,78.5) 89,78.405 89.12,78.285 IC2.23
  Bottom Layer w0.25: R1.2 86.879,79.771 86.879,78.871 87.25,78.5 v1(89,78.5)
NetR2_2: IC2.24 R2.2 | length 4.4
  Top Layer w0.25: IC2.24 89.76,78.165 90,78.405 v1(90,78.5)
  Bottom Layer w0.25: R2.2 88.75,79.75 89.75,79.75 90,79.5 v1(90,78.5)
NetR3_1: IC2.17 R3.1 | length 4.5
  Top Layer w0.25: R3.1 84.1,74.85 85.185,75.935 85.185,76.805 IC2.17
NetR4_1: IC2.19 R4.1 | length 4.9
  Top Layer w0.25: IC2.19 86.465,76.805 86.465,76.116 86.465,76.003 85.75,75.288 85.75,74.21 86.675,73.285 86.675,73.275 87.05,72.9 R4.1
NetR5_2: IC2.14 R5.2 | length 3.6
  Top Layer w0.25: R5.2 82.3,82.95 82.926,82.324 IC2.14
NetY1_1: IC2.3 Y1.1 | length 11.1
  Top Layer w0.25: IC2.3 91.04,80.71 93,78.75 96.75,78.75 98.327,77.173 98.327,76.673 Y1.1
NetY1_2: IC2.2 Y1.2 | length 9.5
  Top Layer w0.25: IC2.2 91.68,81.07 93.25,79.5 96.5,79.5 98.38,81.38 Y1.2
PC_Sense: D2.1 R6.2 U1.5 | length 24.6
  Top Layer w0.25: R6.2 51.734,73.25 D2.1 ; v1(65.75,79.75) 66.084,80.084 U1.5
  Bottom Layer w0.25: D2.1 56.25,76.25 58.75,73.75 64.25,73.75 65.75,75.25 v1(65.75,79.75)
PWR_IND: R10.1 U1.6 | length 5.9
  Top Layer w0.25: U1.6 68.854,81.354 70.4,82.9 R10.1
SWITCH1: J2.3 S1.1 S1.2 U1.13 | length 122.5
  Top Layer w0.225: v1(47.295,111.005) 45.7,112.6 45.7,119.5 49.95,123.75 64.75,123.75 70.85,117.65 70.85,116.63 S1.2 S1.1 ; 64.887,76.887 68.887,76.887
  Top Layer w0.25: v1(48.6,109.1) 64.9,109.1 70,104 70,98 ; U1.13 64.107,76.274 64.158,76.325 64.325,76.325 64.886,76.886 ; 68.887,76.887 77.982,85.982 77.982,96.832 77.909,96.905 76,98.815 76,98.854 70.854,98.854 70,98 ; J2.3 70,96.382 70,98
  Bottom Layer w0.25: v1(47.295,111.005) 47.362,110.938 47.362,110.338 v1(48.6,109.1)
SWITCH2: J2.4 S2.1 S2.2 U1.12 | length 110
  Top Layer w0.225: 64.457,78 66.216,78 66.405,78.189 68.689,78.189
  Top Layer w0.25: U1.12 64.001,77.544 64.457,78 ; 68.689,78.189 76.5,86 76.5,97 75.5,98 73,98 72.383,97.383 J2.4 ; v1(77.9,104.5) 83.25,109.85 83.25,115.912 cw(c85.95,116.28) 83.25,116.648 83.25,121.65 84.3,122.7 110.7,122.7 115.25,118.15 115.25,116.825 115.795,116.28 S2.1@125.052,116.28
  Bottom Layer w0.25: J2.4 72.383,98.983 v1(77.9,104.5)
SWITCH3: S3.1 S3.2 U1.11 | length 126.3
  Top Layer w0.25: U1.11 61.314,78.814 60.907,78.407 53.093,78.407 47,84.5 32.146,84.5 30.5,82.854 30.5,53.7 40.95,43.25 65.25,43.25 71.7,49.7 S3.1 71.75,51.37 v1(71.75,52.75) ; v1(80.75,52.75) 80.75,51.37 S3.2
  Bottom Layer w0.25: v1(71.75,52.75) v1(80.75,52.75)
SWITCH4: S4.1 S4.2 U1.3 | length 188.9
  Top Layer w0.225: 61.068,76.932 63.516,76.932 63.542,76.958
  Top Layer w0.25: v1(32,50.25) 32,50.193 40.193,42 68.5,42 70.5,40 83.25,40 84.35,41.1 114.9,41.1 116.2,39.8 121.5,39.8 122.7,41 122.7,49.1 120.48,51.32 ; v1(32,54.75) 32,57 31.3,57.7 31.3,82.4 32.7,83.8 46.4,83.8 52.7,77.5 58.5,77.5 59.068,76.932 61.068,76.932 ; 63.542,76.958 64.322,76.958 64.908,77.544 U1.3 ; S4.1@116.45,51.32 120.48,51.32 ; S4.2@125.55,51.32 120.48,51.32
  Bottom Layer w0.25: v1(32,50.25) v1(32,54.75)
USB1_5V: C3.2 F1.2 J3.9 J6.9 R12.1 | length 74.5
  Top Layer w0.8: v1(72.25,112.5) R12.1 ; J3.9 106.05,117.7 106.875,116.875 C3.2@106.875,110.75
  Bottom Layer w0.8: J6.9 59.71,119.75 66.25,119.75 66.75,120.25 ; v1(72.25,112.5) 70.75,112.5 69.5,113.75 69.5,117.5 66.75,120.25 ; J3.9 95.8,124.5 71,124.5 66.75,120.25
USB1_D_N: IC2.10 J6.8 | length 57.5
  Top Layer w0.305: J6.8 54.883,117.7 53.783,116.6 53.783,116.248 54.683,115.348 54.683,114.2 53.783,113.3 53.783,112.221 53.961,112.043 66.542,112.043 80.354,98.231 80.892,97.692 86.518,92.067 86.518,82.366 IC2.10
USB1_D_P: IC2.11 J6.7 | length 57.5
  Top Layer w0.305: J6.7 52.127,117.7 53.227,116.6 53.227,116.248 52.327,115.348 52.327,114.2 53.227,113.3 53.227,111.991 53.731,111.488 66.312,111.488 79.961,97.839 80.5,97.3 85.962,91.838 85.962,82.366 IC2.11
USB2_5V: C7.2 F3.2 J4.9 J5.9 R14.1 | length 111
  Top Layer w0.8: J5.9 52.5,45.25 v2(63.5,45.25) 63.5,47.75 62.25,49 62.25,51.5 65.75,55 R14.1 ; J4.9 94.414,48.276 94.414,46.921 94.836,46.5 103.75,46.5 107,49.75 107,52 108.75,53.75 127.998,53.75 130.339,56.091
  Bottom Layer w0.8: v2(63.5,45.25) 91.14,45.25 J4.9
USB2_D_N: IC2.8 J3.8 | length 47.5
  Top Layer w0.305: IC2.8 87.798,82.366 87.798,92.987 84.5,96.285 84.5,105 91.25,111.75 95.25,111.75 ; 95.48,111.75 97.914,111.75 98.723,112.559 98.723,113.25 99.623,114.15 99.623,115.348 98.933,116.038 98.901,116.038 98.723,116.216 98.723,116.593 J3.8
USB2_D_P: IC2.9 J3.7 | length 47.8
  Top Layer w0.305: IC2.9 87.242,82.366 87.242,92.758 87,93 83.945,96.055 83.945,105.23 91.02,112.305 97.684,112.305 98.167,112.788 98.167,113.25 97.267,114.15 97.267,115.348 97.957,116.038 97.989,116.038 98.167,116.216 98.167,116.593 J3.7
USB3_D_N: IC2.6 J4.8 | length 56.3
  Top Layer w0.305: IC2.6 89.078,82.366 89.078,84.078 91.9,86.9 101.321,86.9 101.5,86.721 101.5,68.6 98.687,65.787 98.167,65.267 98.167,52.7 97.267,51.8 97.267,50.752 98.167,49.852 98.167,49.507 J4.8
USB3_D_P: IC2.7 J4.7 | length 58.2
  Top Layer w0.305: IC2.7 88.522,82.366 88.522,84.307 91.67,87.455 101.551,87.455 102.055,86.951 102.055,68.37 99.242,65.558 98.723,65.038 98.723,52.7 99.623,51.8 99.623,50.752 98.723,49.852 98.723,49.507 J4.7
USB4_D_N: IC2.4 J5.8 | length 88.8
  Top Layer w0.305: J5.8 52.127,48.4 53.227,49.5 53.227,49.852 52.327,50.752 52.327,51.8 53.245,52.717 53.245,59.33 56.27,62.355 90.626,62.355 100,71.729 100,84.921 99.821,85.1 92.018,85.1 90.358,83.439 90.358,82.366 IC2.4
USB4_D_P: IC2.5 J5.7 | length 90.6
  Top Layer w0.305: J5.7 54.883,48.4 53.783,49.5 53.783,49.852 54.683,50.752 54.683,51.8 53.8,52.683 53.8,59.1 56.5,61.8 90.856,61.8 100.555,71.499 100.555,85.151 100.051,85.655 91.789,85.655 89.802,83.669 89.802,82.366 IC2.5
USB_PW_CONN1: R11.1 U1.9 U1.10 | length 4.3
  Top Layer w0.25: R11.1 61.447,81.811 61.904,81.354 U1.9 U1.10
USB_PW_CONN3: R15.1 U1.7 U1.8 | length 8.3
  Top Layer w0.305: U1.8 U1.7 67.294,86.056 R15.1
USB_REG1: IC1.5 Q1.3 R9.1 | length 182.5
  Top Layer w0.3: v1(32,117.75) 31,117.75 26.75,113.5 26.75,94.75 29.25,92.25 37,92.25 39,90.25 39,87.176 39.176,87 51.074,87 51.25,86.824 51.25,81.5 52.226,80.524 52.987,80.524 R9.1 54.136,80.511 54.825,81.2 Q1.3 ; v1(48.75,120.75) 59.75,120.75 62,118.5 62,115.25 64,113.25 66.75,113.25 76.75,103.25 80.25,103.25 89.25,112.25 89.25,117.75 92,120.5 111.5,120.5 114.25,117.75 114.25,108.095 116.35,105.995 IC1.5
  Bottom Layer w0.3: v1(32,117.75) 35,120.75 v1(48.75,120.75)
USB_REG2: IC3.5 Q2.3 R13.1 | length 225.7
  Top Layer w0.25: v1(49,85.75) 29.146,85.75 27.5,84.104 27.5,53.25 41.5,39.25 86.426,39.25 87.176,40 v1(102,40) ; v1(56.25,85.75) 56.811,86.311 R13.1 ; v1(105.25,53.5) 105.25,54.75 103.75,56.25 103.75,83.5 v2(109.75,89.5) ; v2(123.5,79.5) 124.485,79.5 124.85,79.865 IC3.5
  Top Layer w0.305: R13.1 60.826,86.25 61.975,86.25 62.625,86.9 Q2.3
  Bottom Layer w0.25: v1(49,85.75) v1(56.25,85.75) ; v1(102,40) 105.25,43.25 v1(105.25,53.5) ; v2(109.75,89.5) 120.25,89.5 123.5,86.25 v2(123.5,79.5)
VPP: P2.2 U1.4 | length 22.7
  Top Layer w0.3: P2.2@67.25,92.25 67.25,90.75 68,90 72.5,90 74.5,88 74.5,85 68.359,78.859 67.34,78.859 U1.4
pads on no net: IC2.25 IC2.27 J3.1 J3.2 J3.3 J3.4 J3.5 J4.1 J4.2 J4.3 J4.4 J4.5 J5.1 J5.2 J5.3 J5.4 J5.5 J6.1 J6.2 J6.3 J6.4 J6.5 P1.1 P1.2 P1.3 P1.4 P1.5 U1.2

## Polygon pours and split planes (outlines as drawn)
GND on Top Layer "GND_L01_P022" (solid, pour order 22): 26,127 cw(c27,127) 27,128 135,128 cw(c135,127) 136,127 136,39.25 cw(c134.75,39.25) 134.75,38 27,38 cw(c27,39) 26,39
USB2_5V on Top Layer "USB2_5V_L01_P018" (solid, pour order 18): 128.75,63.75 127.75,62.75 127.75,55.5 129,54.25 131.5,54.25 133,55.75 133,63.25 132.5,63.75
FB2 on Top Layer "FB2_L01_P017" (solid, pour order 17): 111.75,71 111,70.25 111,66.25 114.5,62.75 114.5,59 116.5,57 125.25,57 127,58.75 127,63.25 126.25,64 122,64 120.25,65.75 120.25,69.5 118.75,71
NetD3_1 on Top Layer "NETD3_1_L01_P016" (solid, pour order 16): 130.5,78 130.75,78.25 130.75,81.25 129.75,82.25 117,82.25 114.25,85 114.25,87 113.75,87.5 110.75,87.5 110,86.75 110,78.25 112.25,76 121.25,76 122,76.75 122,80 123,81 128.75,81 129,80.75 129,78
USB1_5V on Top Layer "USB1_5V_L01_P015" (solid, pour order 15): 107.25,112 107.5,111.75 107.5,105.75 105.5,103.75 102.25,103.75 102,104 102,109.5 103,110.5 105,110.5 105,111.5 105.5,112
FB1 on Top Layer "FB1_L01_P014" (solid, pour order 14): 110.5,110.5 110.75,110.5 112.25,110.5 113,109.75 113,104.5 110,101.5 105.75,101.5 104.75,100.5 104.75,93.5 101.75,90.5 91.75,90.5 91.75,96.25 95.75,96.25 99,99.5 99,100.5 101.25,102.75 106.5,102.75 109.25,105.5 109.25,110.25 109.5,110.5
NetD1_1 on Top Layer "NETD1_1_L01_P013" (solid, pour order 13): 121.5,113 120.75,112.25 120.75,103.25 118,100.5 110.75,100.5 109.75,99.5 109.75,94.75 110.75,93.75 113.5,93.75 114.75,95 114.75,98.25 115.5,99 121,99 122.25,100.25 122.25,107.25 123.25,108.25 124.5,108.25 125.25,109 125.25,112.5 124.75,113
+5V on Top Layer "Top Layer-+5V" (solid, pour order 6): 50.75,98 51,97.75 56.5,97.75 59.25,95 62.25,95 63.5,93.75 63.5,91.5 64,91 65.75,91 65.75,91.25 65.75,91.5 65.75,98 63.25,100.5 60,100.5 60,107 59.5,107.5 57.25,107.5 56.75,107 56.75,103 57.25,102.5 57.25,100.5 56.25,99.5 51,99.5 50.75,99.25
+12V on Top Layer "Top Layer-+12V" (solid, pour order 3): 43.5,93.25 47,93.25 47.75,92.75 47.75,91.25 50,89 53.5,89 54.75,90.25 54.75,96.25 53.75,97.25 51,97.25 49.25,95.5 45.5,95.5 45.5,97.5 46,98 49,98 49.5,98.5 49.5,104.75 49.25,105 44.5,105 43.5,104 43.5,98 43,97.5 42,97.5 41.75,97.25 41.75,93.25 41,92.5 41,90.5 41.75,89.75 42.5,89.75 43.5,90.75
NetF2_1 on Top Layer "NETF2_1_L01_P000" (solid, pour order 0): 28,103.5 28,110 29.5,111.5 35.5,111.5 37,110 37,105.5 37.5,105 42.5,105 43,104.5 43,98.5 42.5,98 39.5,98 36.5,101 35,102.5 29,102.5
GND on Bottom Layer "GND_L02_P021" (solid, pour order 21): 26,127 cw(c27,127) 27,128 135,128 cw(c135,127) 136,127 136,39.25 cw(c134.75,39.25) 134.75,38 27,38 cw(c27,39) 26,39

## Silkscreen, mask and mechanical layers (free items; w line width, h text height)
Top Overlay:
  drawing of 135 lines, arcs and shapes, not listed
  text "USB" at 72.7,121.965 h2
  text "USB" at 119.45,121.965 h2
  text "PWR" at 75.7,121.956 h2
  text "12VIN" at 27.3,112.114 h5
  text "D-SUB USB 2" at 93.294,111.219 h2.5
  text "D-SUB USB 1" at 48.352,111.119 h2.5
  text "ICSP" at 68.2,98.219 h2.5
  text "PMODE" at 72.2,90.215 h2
  text "PWR" at 75.794,84.95 h2 r90
  text "D-SUB USB HOST" at 40.681,69.034 h2.5 r90
  text "D-SUB USB 4" at 48.352,53.719 h2.5
  text "D-SUB USB 3" at 93.292,53.719 h2.5
  text "USB" at 76.2,44.215 h2
  text "USB" at 119.15,44.215 h2
  text "PWR" at 72.7,44.206 h2
  text "DSUB USB HUB V2" at 115.18,38.365 h2
Bottom Overlay:
  text "01-2025" at 47.246,39.504 h1.52
Mechanical 1:
  circle w0.013: c31,43 r2
  circle w0.013: c31,43 r2
  circle w0.013: c131,43 r2
  circle w0.013: c131,43 r2
  circle w0.013: c131,123 r2
  circle w0.013: c131,123 r2
  circle w0.013: c31,123 r2
  circle w0.013: c31,123 r2
  lines w0.25: 26,39 ccw(c27,39) 27,38 134.73,38 ccw(c134.73,39.27) 136,39.27 136,121 136,127 ccw(c135,127) 135,128 27,128 ccw(c27,127) 26,127 26,39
